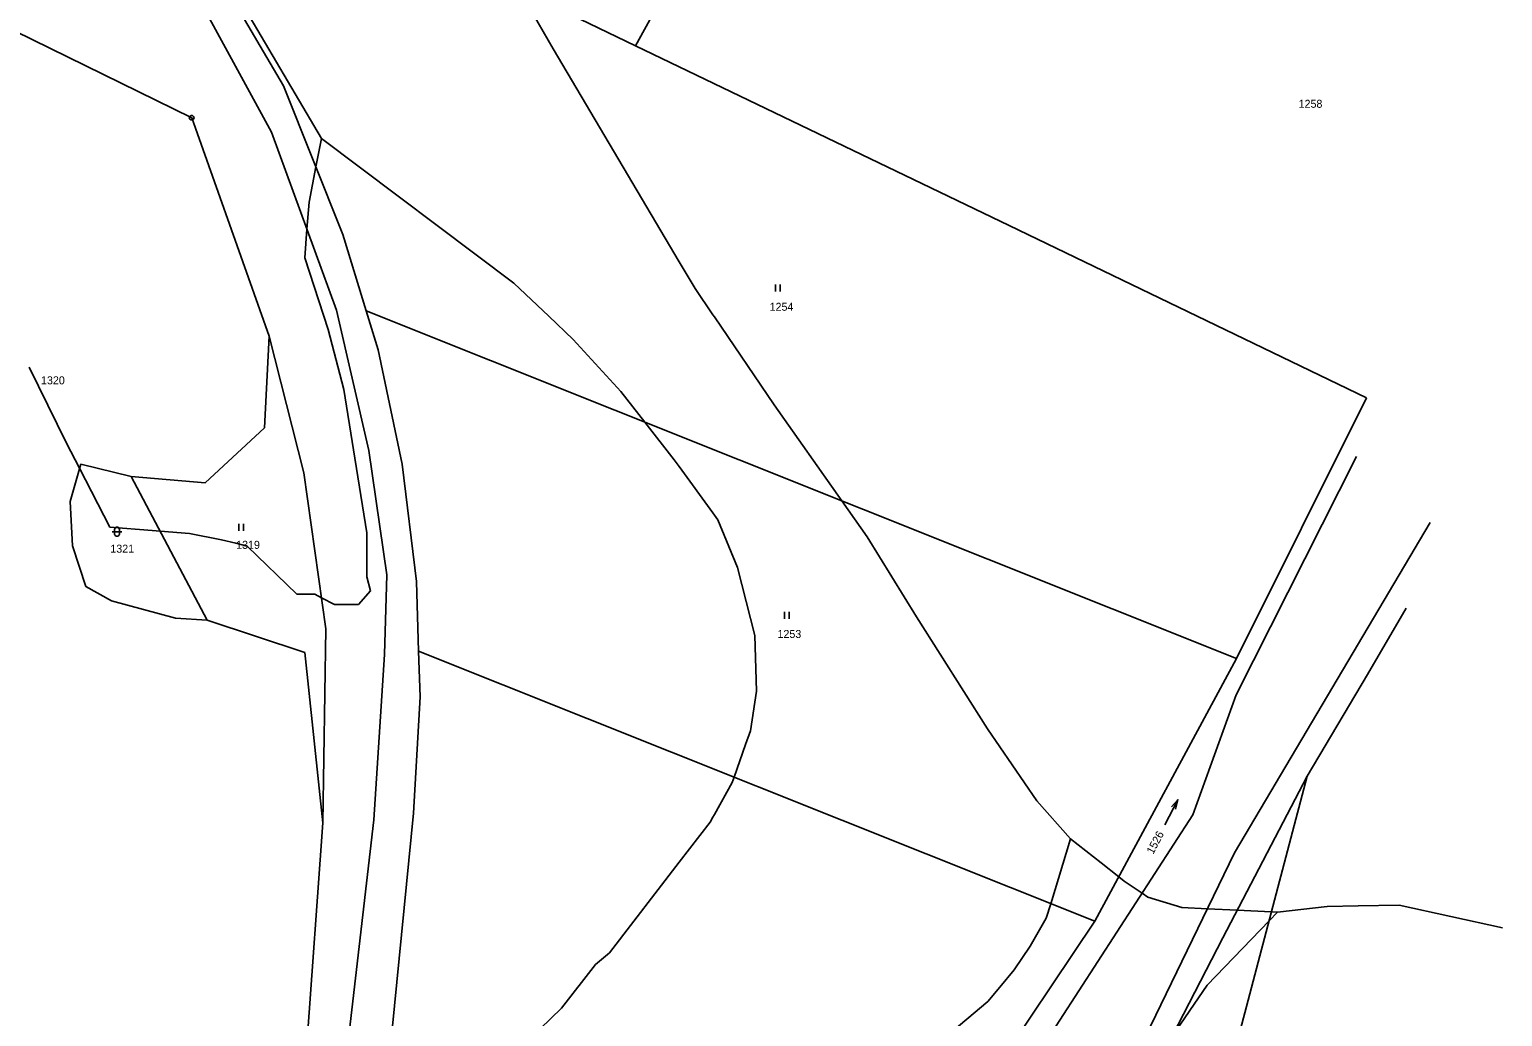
# Model space of a CAD drawing. Extents: x -792913 to -792113, y -1112764 to -1111548.
# Drawn here: x -792425.8 to -792112.8, y -1112549.9 to -1112340 of the extents above; entities that cross this region are included whole.
import ezdxf

# ---------------------------------------------------------------- set-up
doc = ezdxf.new("R2010")
doc.units = 0
for name, color, linetype in [('Vrstva 1', 7, 'Continuous'), ('Vrstva 11', 7, 'Continuous'), ('Vrstva 2', 7, 'Continuous'), ('Vrstva 3', 7, 'Continuous'), ('Vrstva 8', 7, 'Continuous')]:
    doc.layers.add(name, color=color, linetype=linetype)

msp = doc.modelspace()

# ---------------------------------------------------------------- linework, layer by layer
at = {"layer": 'Vrstva 1'}
for p, q in [((-792297.07, -1112343.48), (-792243.89, -1112247.46)), ((-792398.63, -1112306.46), (-792371.86, -1112351.99)), ((-792322.81, -1112331.08), (-792297.07, -1112343.48)), ((-792436.12, -1112336.84), (-792391.37, -1112358.8)), ((-792374.42, -1112361.83), (-792387.56, -1112337.7)), ((-792217.69, -1112381.73), (-792297.07, -1112343.48)), ((-792371.86, -1112351.99), (-792359.27, -1112383.59)), ((-792391.37, -1112358.8), (-792374.88, -1112405.24)), ((-792360.6, -1112399.73), (-792374.42, -1112361.83)), ((-792359.27, -1112383.59), (-792354.28, -1112399.87)), ((-792141.73, -1112418.34), (-792217.69, -1112381.73)), ((-792217.69, -1112381.73), (-792217.69, -1112381.73)), ((-792353.76, -1112429.55), (-792360.6, -1112399.73)), ((-792169.35, -1112473.74), (-792354.28, -1112399.87)), ((-792354.28, -1112399.87), (-792351.75, -1112408.11)), ((-792375.89, -1112424.71), (-792374.88, -1112405.24)), ((-792374.88, -1112405.24), (-792367.54, -1112434.25)), ((-792351.75, -1112408.11), (-792346.63, -1112432.41)), ((-792169.35, -1112473.74), (-792141.73, -1112418.34)), ((-792141.73, -1112418.34), (-792141.73, -1112418.34)), ((-792388.48, -1112436.37), (-792375.89, -1112424.71)), ((-792349.92, -1112455.97), (-792353.76, -1112429.55)), ((-792169.45, -1112481.5), (-792143.84, -1112430.83)), ((-792417.22, -1112440.34), (-792414.96, -1112432.41)), ((-792414.96, -1112432.41), (-792404.24, -1112435.07)), ((-792367.54, -1112434.25), (-792362.84, -1112467.43)), ((-792346.63, -1112432.41), (-792343.63, -1112457.37)), ((-792388.11, -1112465.56), (-792404.24, -1112435.07)), ((-792404.24, -1112435.07), (-792388.48, -1112436.37)), ((-792416.73, -1112449.77), (-792417.22, -1112440.34)), ((-792128.19, -1112444.8), (-792169.77, -1112515.04)), ((-792413.9, -1112458.41), (-792416.73, -1112449.77)), ((-792350.44, -1112472.92), (-792349.92, -1112455.97)), ((-792408.41, -1112461.45), (-792413.9, -1112458.41)), ((-792343.63, -1112457.37), (-792343.17, -1112472.2)), ((-792394.85, -1112465.2), (-792408.41, -1112461.45)), ((-792388.11, -1112465.56), (-792394.85, -1112465.2)), ((-792367.34, -1112472.47), (-792388.11, -1112465.56)), ((-792133.3, -1112463.05), (-792141.53, -1112477.11)), ((-792133.3, -1112463.05), (-792133.3, -1112463.05)), ((-792133.3, -1112463.05), (-792133.3, -1112463.05)), ((-792362.84, -1112467.43), (-792363.48, -1112508.68)), ((-792199.46, -1112529.6), (-792343.17, -1112472.2)), ((-792343.17, -1112472.2), (-792342.86, -1112481.89)), ((-792363.48, -1112508.68), (-792367.34, -1112472.47)), ((-792352.65, -1112508.04), (-792350.44, -1112472.92)), ((-792199.46, -1112529.6), (-792169.35, -1112473.74)), ((-792154.32, -1112498.77), (-792141.53, -1112477.11)), ((-792141.53, -1112477.11), (-792141.53, -1112477.11)), ((-792178.62, -1112506.97), (-792169.45, -1112481.5)), ((-792342.86, -1112481.89), (-792344.24, -1112506.65)), ((-792182.87, -1112606.76), (-792154.32, -1112498.77)), ((-792154.32, -1112498.77), (-792172.3, -1112533.11)), ((-792344.24, -1112506.65), (-792348.78, -1112552.61)), ((-792363.48, -1112508.68), (-792368.29, -1112575.43)), ((-792358.11, -1112555.18), (-792352.65, -1112508.04)), ((-792240.99, -1112603.1), (-792178.62, -1112506.97)), ((-792169.77, -1112515.04), (-792188.74, -1112554.21)), ((-792246.5, -1112599.75), (-792199.46, -1112529.6)), ((-792172.3, -1112533.11), (-792184.15, -1112556.21))]:
    msp.add_line(p, q, dxfattribs=at)
at = {"layer": 'Vrstva 11'}
for p, q in [((-792314.59, -1112344.12), (-792321.85, -1112331.54)), ((-792380.59, -1112334.73), (-792363.82, -1112363.21)), ((-792287.77, -1112389.42), (-792314.59, -1112344.12)), ((-792364.99, -1112369.24), (-792363.82, -1112363.21)), ((-792363.82, -1112363.21), (-792322.92, -1112393.98)), ((-792366.44, -1112376.73), (-792364.99, -1112369.24)), ((-792366.88, -1112382.5), (-792366.44, -1112376.73)), ((-792367.35, -1112388.57), (-792366.88, -1112382.5)), ((-792362.36, -1112403.84), (-792367.35, -1112388.57)), ((-792284.4, -1112395.12), (-792287.77, -1112389.42)), ((-792322.92, -1112393.98), (-792315.5, -1112401)), ((-792280.63, -1112400.66), (-792284.4, -1112395.12)), ((-792315.5, -1112401), (-792310.29, -1112405.93)), ((-792280.31, -1112401.13), (-792280.63, -1112400.66)), ((-792267.6, -1112419.79), (-792280.31, -1112401.13)), ((-792359.04, -1112416.56), (-792362.36, -1112403.84)), ((-792310.29, -1112405.93), (-792300.19, -1112417.01)), ((-792425.92, -1112411.82), (-792417.97, -1112427.96)), ((-792356.98, -1112429.36), (-792359.04, -1112416.56)), ((-792300.19, -1112417.01), (-792295.08, -1112423.52)), ((-792253.23, -1112440.24), (-792267.6, -1112419.79)), ((-792295.08, -1112423.52), (-792288.84, -1112431.48)), ((-792417.97, -1112427.96), (-792415.21, -1112433.3)), ((-792354.14, -1112447.06), (-792356.98, -1112429.36)), ((-792288.84, -1112431.48), (-792287.77, -1112432.95)), ((-792415.21, -1112433.3), (-792408.75, -1112445.8)), ((-792287.77, -1112432.95), (-792280.63, -1112442.81)), ((-792247.86, -1112447.87), (-792253.23, -1112440.24)), ((-792280.63, -1112442.81), (-792280.31, -1112443.25)), ((-792280.31, -1112443.25), (-792279.59, -1112444.24)), ((-792408.75, -1112445.8), (-792399.78, -1112446.54)), ((-792399.78, -1112446.54), (-792398.1, -1112446.68)), ((-792398.1, -1112446.68), (-792391.82, -1112447.19)), ((-792391.82, -1112447.19), (-792385.06, -1112448.51)), ((-792354.19, -1112456.37), (-792354.14, -1112447.06)), ((-792279.59, -1112444.24), (-792275.42, -1112454.43)), ((-792385.06, -1112448.51), (-792382.01, -1112449.24)), ((-792382.01, -1112449.24), (-792379.56, -1112449.83)), ((-792379.56, -1112449.83), (-792369.03, -1112460.06)), ((-792237.37, -1112464.87), (-792247.86, -1112447.87)), ((-792353.36, -1112459.33), (-792354.19, -1112456.37)), ((-792275.42, -1112454.43), (-792271.69, -1112468.84)), ((-792355.92, -1112462.28), (-792353.36, -1112459.33)), ((-792369.03, -1112460.06), (-792365.22, -1112460.09)), ((-792365.22, -1112460.09), (-792363.78, -1112460.83)), ((-792363.78, -1112460.83), (-792361, -1112462.24)), ((-792361, -1112462.24), (-792355.92, -1112462.28)), ((-792222.26, -1112488.68), (-792237.37, -1112464.87)), ((-792271.69, -1112468.84), (-792271.33, -1112480.69)), ((-792271.33, -1112480.69), (-792272.65, -1112489.14)), ((-792272.65, -1112489.14), (-792273.67, -1112492.04)), ((-792211.76, -1112503.99), (-792222.26, -1112488.68)), ((-792273.67, -1112492.04), (-792276.13, -1112498.98)), ((-792276.53, -1112500.11), (-792280.31, -1112506.89)), ((-792276.13, -1112498.98), (-792276.53, -1112500.11)), ((-792204.61, -1112512.08), (-792211.76, -1112503.99)), ((-792281.23, -1112508.54), (-792287.77, -1112517.05)), ((-792280.63, -1112507.46), (-792281.23, -1112508.54)), ((-792280.31, -1112506.89), (-792280.63, -1112507.46)), ((-792204.61, -1112512.08), (-792208.83, -1112525.86)), ((-792198.14, -1112517.19), (-792204.61, -1112512.08)), ((-792287.77, -1112517.05), (-792302.56, -1112536.3)), ((-792194.37, -1112520.16), (-792198.14, -1112517.19)), ((-792193.23, -1112521.06), (-792194.37, -1112520.16)), ((-792189.43, -1112523.63), (-792193.23, -1112521.06)), ((-792188.17, -1112524.48), (-792189.43, -1112523.63)), ((-792180.98, -1112526.65), (-792188.17, -1112524.48)), ((-792208.83, -1112525.86), (-792209.79, -1112528.97)), ((-792175.52, -1112526.92), (-792180.98, -1112526.65)), ((-792169.22, -1112527.23), (-792175.52, -1112526.92)), ((-792161.94, -1112527.59), (-792169.22, -1112527.23)), ((-792162.45, -1112529.51), (-792160.66, -1112527.65)), ((-792160.66, -1112527.65), (-792161.94, -1112527.59)), ((-792150.07, -1112526.46), (-792160.66, -1112527.65)), ((-792143.54, -1112526.33), (-792150.07, -1112526.46)), ((-792134.82, -1112526.16), (-792143.54, -1112526.33)), ((-792112.83, -1112530.98), (-792134.82, -1112526.16)), ((-792209.79, -1112528.97), (-792213.21, -1112534.87)), ((-792175.57, -1112543.19), (-792162.45, -1112529.51)), ((-792213.21, -1112534.87), (-792216.62, -1112539.92)), ((-792302.56, -1112536.3), (-792305.54, -1112538.82)), ((-792305.54, -1112538.82), (-792312.79, -1112548.07)), ((-792216.62, -1112539.92), (-792219.67, -1112543.61)), ((-792219.67, -1112543.61), (-792222.17, -1112546.64)), ((-792183.1, -1112554.16), (-792175.57, -1112543.19)), ((-792222.17, -1112546.64), (-792231.1, -1112554.19)), ((-792312.79, -1112548.07), (-792331.95, -1112566.54))]:
    msp.add_line(p, q, dxfattribs=at)
at = {"layer": 'Vrstva 3'}
for p, q in [((-792267.31, -1112394.25), (-792267.31, -1112395.75)), ((-792266.31, -1112395.75), (-792266.31, -1112394.25)), ((-792381.39, -1112445.09), (-792381.39, -1112446.59)), ((-792380.39, -1112446.59), (-792380.39, -1112445.09)), ((-792265.39, -1112463.8), (-792265.39, -1112465.3)), ((-792264.39, -1112465.3), (-792264.39, -1112463.8)), ((-792184.613, -1112509.072), (-792181.807, -1112503.768))]:
    msp.add_line(p, q, dxfattribs=at)
for points in [[(-792408.25, -1112446.79), (-792406.98, -1112446.79), (-792406.25, -1112446.79)], [(-792183.184, -1112505.302), (-792181.807, -1112503.768), (-792182.3, -1112505.77)]]:
    msp.add_lwpolyline(points, dxfattribs=at)
msp.add_lwpolyline([(-792407.75, -1112446.29), (-792407.65, -1112446), (-792407.4, -1112445.82), (-792407.09, -1112445.82), (-792406.84, -1112446), (-792406.74, -1112446.29), (-792406.74, -1112447.29), (-792406.84, -1112447.58), (-792407.09, -1112447.76), (-792407.4, -1112447.76), (-792407.65, -1112447.58), (-792407.75, -1112447.29)], close=True, dxfattribs=at)
at = {"layer": 'Vrstva 8'}
msp.add_line((-792391.49, -1112358.8), (-792391.25, -1112358.8), dxfattribs=at)
msp.add_lwpolyline([(-792391.22, -1112358.32), (-792390.97, -1112358.5), (-792390.87, -1112358.79), (-792390.97, -1112359.08), (-792391.22, -1112359.26), (-792391.53, -1112359.26), (-792391.78, -1112359.08), (-792391.88, -1112358.79), (-792391.78, -1112358.5), (-792391.53, -1112358.32)], close=True, dxfattribs=at)

# ---------------------------------------------------------------- texts
at = {"layer": 'Vrstva 2'}
for s, p in [('1258', (-792156.167, -1112356.68)), ('1254', (-792268.577, -1112399.83)), ('1320', (-792423.397, -1112415.46)), ('1321', (-792408.667, -1112451.25)), ('1319', (-792381.937, -1112450.43)), ('1253', (-792266.897, -1112469.38))]:
    msp.add_text(s, height=1.7, dxfattribs=at).set_placement(p)
msp.add_text('1526', height=1.7, rotation=62.05133, dxfattribs=at).set_placement((-792187.076, -1112515.473))

doc.saveas('drawing.dxf')
